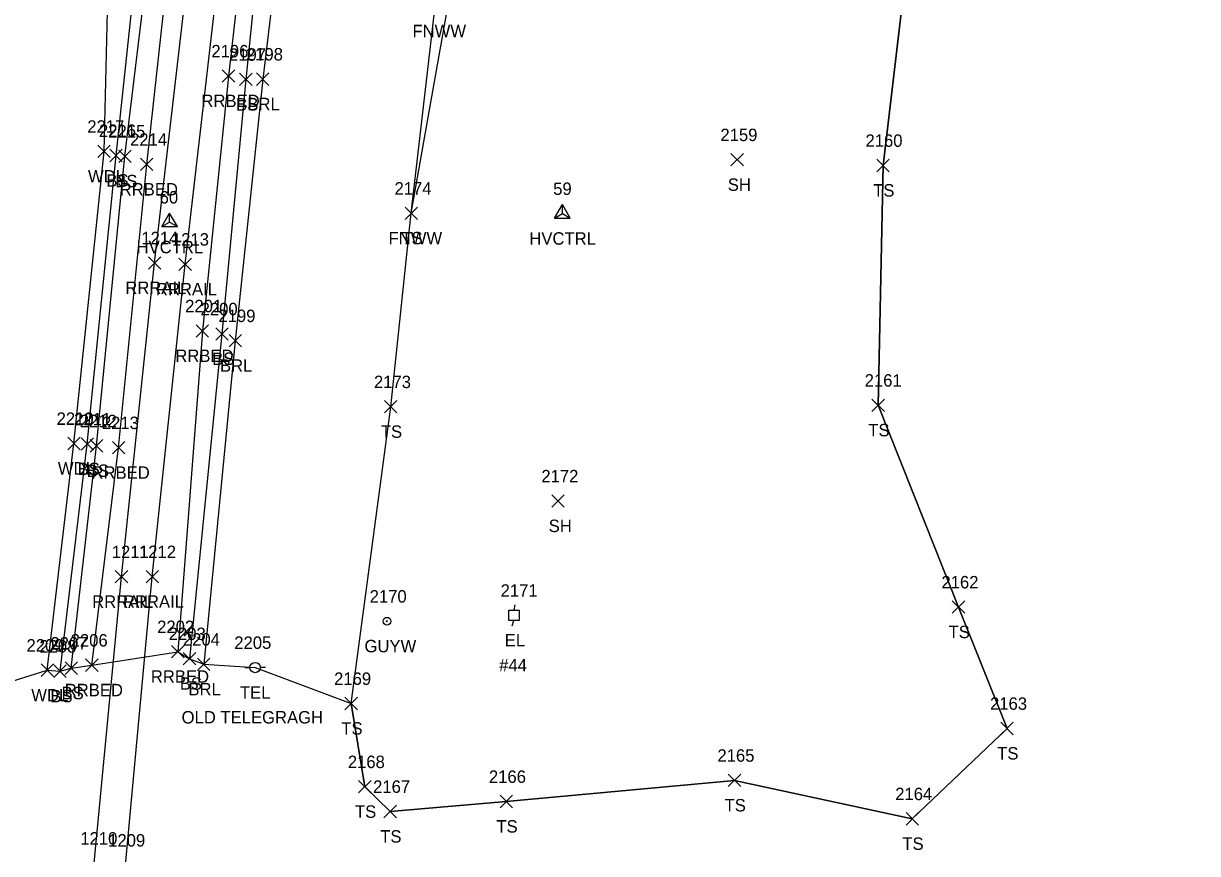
# Model space of a CAD drawing. Extents: x 1754529 to 1755810, y 621660 to 624656.
# Drawn here: x 1755616 to 1755804.8, y 623700.7 to 623834.2 of the extents above; entities that cross this region are included whole.
import ezdxf

# ---------------------------------------------------------------- set-up
doc = ezdxf.new("R2010")
doc.units = 0
for name, color, linetype in [('C_A', 7, 'Continuous'), ('C_I', 7, 'Continuous'), ('CPSM', 7, 'Continuous'), ('L_A', 7, 'Continuous'), ('L_I', 7, 'Continuous'), ('L_TIC', 7, 'Continuous'), ('LABL', 7, 'Continuous'), ('LAWA', 7, 'Continuous'), ('LELB', 7, 'Continuous'), ('LFNC', 7, 'Continuous'), ('LSOGP', 7, 'Continuous'), ('R_A', 7, 'Continuous'), ('R_I', 7, 'Continuous'), ('R_TIC', 7, 'Continuous'), ('RR', 7, 'Continuous'), ('RRB', 7, 'Continuous'), ('U_A', 7, 'Continuous'), ('U_C', 7, 'Continuous'), ('U_I', 7, 'Continuous'), ('UEPT', 7, 'Continuous'), ('UP', 7, 'Continuous'), ('UPGW', 7, 'Continuous')]:
    doc.layers.add(name, color=color, linetype=linetype)

msp = doc.modelspace()

# ---------------------------------------------------------------- linework, layer by layer
at = {"layer": 'CPSM'}
for p, q in [((1755701.4, 623802.89), (1755702.65, 623805.06)), ((1755703.9, 623802.89), (1755702.65, 623805.06)), ((1755702.65, 623803.61), (1755702.65, 623805.06)), ((1755638.27, 623801.51), (1755639.52, 623803.68)), ((1755640.77, 623801.51), (1755639.52, 623803.68)), ((1755639.52, 623802.23), (1755639.52, 623803.68)), ((1755701.4, 623802.89), (1755702.65, 623803.61)), ((1755701.4, 623802.89), (1755703.9, 623802.89)), ((1755702.65, 623803.61), (1755702.65, 623803.61)), ((1755702.65, 623803.61), (1755703.9, 623802.89)), ((1755638.27, 623801.51), (1755639.52, 623802.23)), ((1755638.27, 623801.51), (1755640.77, 623801.51)), ((1755639.52, 623802.23), (1755639.52, 623802.23)), ((1755639.52, 623802.23), (1755640.77, 623801.51))]:
    msp.add_line(p, q, dxfattribs=at)
at = {"layer": 'L_TIC'}
for points in [[(1755650.77, 623824.19), (1755652.77, 623826.19)], [(1755652.77, 623824.19), (1755650.77, 623826.19)], [(1755653.48, 623824.24), (1755655.48, 623826.24)], [(1755655.48, 623824.24), (1755653.48, 623826.24)], [(1755627.98, 623812.62), (1755629.98, 623814.62)], [(1755629.98, 623812.62), (1755627.98, 623814.62)], [(1755629.92, 623811.95), (1755631.92, 623813.95)], [(1755631.92, 623811.95), (1755629.92, 623813.95)], [(1755631.35, 623811.84), (1755633.35, 623813.84)], [(1755633.35, 623811.84), (1755631.35, 623813.84)], [(1755729.76, 623811.27), (1755731.76, 623813.27)], [(1755731.76, 623811.27), (1755729.76, 623813.27)], [(1755753.21, 623810.35), (1755755.21, 623812.35)], [(1755755.21, 623810.35), (1755753.21, 623812.35)], [(1755677.37, 623802.67), (1755679.37, 623804.67)], [(1755679.37, 623802.67), (1755677.37, 623804.67)], [(1755677.37, 623802.67), (1755679.37, 623804.67)], [(1755679.37, 623802.67), (1755677.37, 623804.67)], [(1755646.93, 623783.26), (1755648.93, 623785.26)], [(1755648.93, 623783.26), (1755646.93, 623785.26)], [(1755649.07, 623782.16), (1755651.07, 623784.16)], [(1755651.07, 623782.16), (1755649.07, 623784.16)], [(1755674.07, 623771.54), (1755676.07, 623773.54)], [(1755676.07, 623771.54), (1755674.07, 623773.54)], [(1755752.42, 623771.78), (1755754.42, 623773.78)], [(1755754.42, 623771.78), (1755752.42, 623773.78)], [(1755623.14, 623765.63), (1755625.14, 623767.63)], [(1755625.14, 623765.63), (1755623.14, 623767.63)], [(1755625.29, 623765.54), (1755627.29, 623767.54)], [(1755627.29, 623765.54), (1755625.29, 623767.54)], [(1755626.77, 623765.25), (1755628.77, 623767.25)], [(1755628.77, 623765.25), (1755626.77, 623767.25)], [(1755700.97, 623756.38), (1755702.97, 623758.38)], [(1755702.97, 623756.38), (1755700.97, 623758.38)], [(1755765.33, 623739.32), (1755767.33, 623741.32)], [(1755767.33, 623739.32), (1755765.33, 623741.32)], [(1755641.72, 623731.01), (1755643.72, 623733.01)], [(1755643.72, 623731.01), (1755641.72, 623733.01)], [(1755618.86, 623729.16), (1755620.86, 623731.16)], [(1755620.86, 623729.16), (1755618.86, 623731.16)], [(1755620.92, 623729), (1755622.92, 623731)], [(1755622.92, 623729), (1755620.92, 623731)], [(1755622.71, 623729.49), (1755624.71, 623731.49)], [(1755624.71, 623729.49), (1755622.71, 623731.49)], [(1755644, 623730.12), (1755646, 623732.12)], [(1755646, 623730.12), (1755644, 623732.12)], [(1755667.71, 623723.8), (1755669.71, 623725.8)], [(1755669.71, 623723.8), (1755667.71, 623725.8)], [(1755773.14, 623719.79), (1755775.14, 623721.79)], [(1755775.14, 623719.79), (1755773.14, 623721.79)], [(1755669.91, 623710.42), (1755671.91, 623712.42)], [(1755671.91, 623710.42), (1755669.91, 623712.42)], [(1755729.32, 623711.44), (1755731.32, 623713.44)], [(1755731.32, 623711.44), (1755729.32, 623713.44)], [(1755692.64, 623708.04), (1755694.64, 623710.04)], [(1755694.64, 623708.04), (1755692.64, 623710.04)], [(1755673.97, 623706.43), (1755675.97, 623708.43)], [(1755675.97, 623706.43), (1755673.97, 623708.43)], [(1755757.9, 623705.26), (1755759.9, 623707.26)], [(1755759.9, 623705.26), (1755757.9, 623707.26)]]:
    msp.add_lwpolyline(points, dxfattribs=at)
at = {"layer": 'LABL'}
msp.add_lwpolyline([(1755679.41, 624018.81), (1755672.58, 623965.56), (1755666.1, 623922.5), (1755661.18, 623881.21), (1755654.48, 623825.24), (1755650.07, 623783.16), (1755645, 623731.12)], dxfattribs=at)
at = {"layer": 'LAWA'}
msp.add_lwpolyline([(1755619.86, 623730.16), (1755624.14, 623766.63), (1755628.98, 623813.62), (1755630.26, 623865.45), (1755633.57, 623899.24), (1755639.63, 623936.66), (1755644.4, 623954.08), (1755644.69, 623975.95), (1755648.86, 624008.69), (1755659.88, 624048.72)], dxfattribs=at)
at = {"layer": 'LELB'}
for points in [[(1755621.92, 623730), (1755626.29, 623766.54), (1755630.92, 623812.95), (1755636.58, 623865.85), (1755640.01, 623898.18), (1755646.5, 623937.01), (1755651.75, 623974.07), (1755657.7, 624011.52), (1755662.62, 624047.83)], [(1755623.71, 623730.49), (1755627.77, 623766.25), (1755632.35, 623812.84), (1755638.78, 623865.94), (1755642.85, 623897.02), (1755648.59, 623936.85), (1755653.51, 623973.7), (1755658.98, 624011.28), (1755664.45, 624047.05)], [(1755677.5, 624019.45), (1755668.5, 623966.15), (1755663.47, 623922.18), (1755657.52, 623881.88), (1755651.77, 623825.19), (1755647.93, 623784.26), (1755642.72, 623732.01)], [(1755759.64, 623857.27), (1755754.21, 623811.35), (1755753.42, 623772.78), (1755766.33, 623740.32), (1755774.14, 623720.79), (1755758.9, 623706.26), (1755730.32, 623712.44), (1755693.64, 623709.04), (1755674.97, 623707.43), (1755670.91, 623711.42), (1755668.71, 623724.8), (1755675.07, 623772.54), (1755678.37, 623803.67), (1755691.4, 623877.41), (1755687.83, 623918.52), (1755691.1, 623961.39)]]:
    msp.add_lwpolyline(points, dxfattribs=at)
at = {"layer": 'LFNC'}
msp.add_lwpolyline([(1755678.37, 623803.67), (1755682.22, 623836.98), (1755686.15, 623877.78), (1755687.83, 623918.52)], dxfattribs=at)
at = {"layer": 'LSOGP'}
msp.add_lwpolyline([(1755585.86, 623719.5), (1755619.86, 623730.16), (1755621.92, 623730), (1755623.71, 623730.49), (1755627.02, 623730.97), (1755640.85, 623733.14), (1755642.72, 623732.01), (1755645, 623731.12), (1755653.26, 623730.59), (1755668.71, 623724.8), (1755670.91, 623711.42), (1755674.97, 623707.43), (1755693.64, 623709.04), (1755730.32, 623712.44), (1755758.9, 623706.26), (1755774.14, 623720.79), (1755766.33, 623740.32), (1755753.42, 623772.78), (1755754.21, 623811.35), (1755759.64, 623857.27)], dxfattribs=at)
at = {"layer": 'R_TIC'}
for points in [[(1755647.99, 623824.74), (1755649.99, 623826.74)], [(1755649.99, 623824.74), (1755647.99, 623826.74)], [(1755634.85, 623810.52), (1755636.85, 623812.52)], [(1755636.85, 623810.52), (1755634.85, 623812.52)], [(1755636.11, 623794.68), (1755638.11, 623796.68)], [(1755638.11, 623794.68), (1755636.11, 623796.68)], [(1755641.03, 623794.46), (1755643.03, 623796.46)], [(1755643.03, 623794.46), (1755641.03, 623796.46)], [(1755643.79, 623783.74), (1755645.79, 623785.74)], [(1755645.79, 623783.74), (1755643.79, 623785.74)], [(1755630.33, 623764.95), (1755632.33, 623766.95)], [(1755632.33, 623764.95), (1755630.33, 623766.95)], [(1755630.78, 623744.19), (1755632.78, 623746.19)], [(1755632.78, 623744.19), (1755630.78, 623746.19)], [(1755635.73, 623744.2), (1755637.73, 623746.2)], [(1755637.73, 623744.2), (1755635.73, 623746.2)], [(1755639.85, 623732.14), (1755641.85, 623734.14)], [(1755641.85, 623732.14), (1755639.85, 623734.14)], [(1755626.02, 623729.97), (1755628.02, 623731.97)], [(1755628.02, 623729.97), (1755626.02, 623731.97)]]:
    msp.add_lwpolyline(points, dxfattribs=at)
at = {"layer": 'RR'}
for points in [[(1755627.39, 623699.11), (1755631.78, 623745.19), (1755637.11, 623795.68), (1755642.45, 623841.98), (1755647.89, 623885.58), (1755654.04, 623931.54), (1755660.61, 623977.9), (1755666.29, 624016.06), (1755672.3, 624053.9), (1755679.64, 624097.76), (1755687.07, 624139.84), (1755694.5, 624180.62), (1755701.72, 624217.85), (1755709.31, 624256.23), (1755717.86, 624297.53), (1755724.56, 624328.91), (1755733.93, 624371.3), (1755743.26, 624412.4), (1755753.41, 624456.24), (1755764.06, 624501.26), (1755774.99, 624547.18), (1755787.52, 624599.52), (1755800.05, 624650.73)], [(1755632.43, 623698.79), (1755636.73, 623745.2), (1755642.03, 623795.46), (1755647.4, 623842), (1755652.81, 623884.87), (1755658.94, 623931.22), (1755665.5, 623977.61), (1755671.13, 624015.19), (1755677.17, 624053.23), (1755684.42, 624096.54), (1755692.03, 624139.27), (1755699.47, 624179.9), (1755706.47, 624216.55), (1755714.07, 624254.59), (1755722.62, 624295.88), (1755729.35, 624327.29), (1755738.69, 624369.66), (1755747.98, 624411.22), (1755758.14, 624454.7), (1755769.01, 624500.51), (1755779.76, 624545.7), (1755792.4, 624598.28), (1755804.75, 624649.74)]]:
    msp.add_lwpolyline(points, dxfattribs=at)
at = {"layer": 'RRB'}
for points in [[(1755627.02, 623730.97), (1755631.33, 623765.95), (1755635.85, 623811.52), (1755641.9, 623866.82), (1755645.93, 623895.6), (1755651.57, 623936.6), (1755656.7, 623972.5), (1755662.71, 624010.8), (1755667.32, 624046.39)], [(1755675.92, 624019.67), (1755666.85, 623966.35), (1755661.03, 623923.27), (1755655.33, 623881.88), (1755648.99, 623825.74), (1755644.79, 623784.74), (1755640.85, 623733.14)]]:
    msp.add_lwpolyline(points, dxfattribs=at)
at = {"layer": 'UEPT'}
for p, q in [((1755695.03, 623740.65), (1755694.86, 623739.81)), ((1755694.03, 623738.15), (1755694.03, 623739.81)), ((1755694.03, 623739.81), (1755695.69, 623739.81)), ((1755694.86, 623738.98), (1755694.86, 623738.98)), ((1755695.69, 623739.81), (1755695.69, 623738.15)), ((1755695.69, 623738.15), (1755694.03, 623738.15)), ((1755694.61, 623737.31), (1755694.86, 623738.15))]:
    msp.add_line(p, q, dxfattribs=at)
at = {"layer": 'UP'}
for p, q in [((1755651.6, 623730.58), (1755652.43, 623730.58)), ((1755653.26, 623730.59), (1755653.26, 623730.59)), ((1755654.93, 623730.59), (1755654.1, 623730.59)), ((1755654.1, 623730.59), (1755654.1, 623730.59)), ((1755654.93, 623730.59), (1755654.93, 623730.59))]:
    msp.add_line(p, q, dxfattribs=at)
msp.add_circle((1755653.26, 623730.59), 0.833, dxfattribs=at)
at = {"layer": 'UPGW'}
for radius in [0.625, 0.0833]:
    msp.add_circle((1755674.46, 623738.04), radius, dxfattribs=at)

# ---------------------------------------------------------------- texts
at = {"layer": 'C_A'}
for p in [(1755697.35, 623798.61), (1755634.21, 623797.23)]:
    msp.add_text('HVCTRL', height=2, dxfattribs=at).set_placement(p)
at = {"layer": 'C_I'}
for s, p in [('59', (1755701.18, 623806.61)), ('60', (1755637.92, 623805.23))]:
    msp.add_text(s, height=2, dxfattribs=at).set_placement(p)
at = {"layer": 'L_A'}
for s, p in [('FNWW', (1755678.56, 623831.98)), ('BS', (1755650.21, 623820.19)), ('BRL', (1755652.02, 623820.24)), ('WDL', (1755626.4, 623808.62)), ('BS', (1755629.36, 623807.95)), ('BS', (1755630.79, 623807.84)), ('SH', (1755729.25, 623807.27)), ('TS', (1755752.62, 623806.35)), ('FNWW', (1755674.72, 623798.67)), ('TS', (1755676.78, 623798.67)), ('BS', (1755646.37, 623779.26)), ('BRL', (1755647.62, 623778.16)), ('TS', (1755673.48, 623767.54)), ('TS', (1755751.83, 623767.78)), ('WDL', (1755621.56, 623761.63)), ('BS', (1755624.73, 623761.54)), ('BS', (1755626.21, 623761.25)), ('SH', (1755700.46, 623752.38)), ('TS', (1755764.74, 623735.32)), ('BS', (1755641.16, 623727.01)), ('WDL', (1755617.28, 623725.16)), ('BS', (1755620.36, 623725)), ('BS', (1755622.15, 623725.49)), ('BRL', (1755642.54, 623726.12)), ('TS', (1755667.12, 623719.8)), ('TS', (1755772.55, 623715.79)), ('TS', (1755669.32, 623706.42)), ('TS', (1755728.73, 623707.44)), ('TS', (1755673.38, 623702.43)), ('TS', (1755692.05, 623704.04)), ('TS', (1755757.31, 623701.26))]:
    msp.add_text(s, height=2, dxfattribs=at).set_placement(p)
at = {"layer": 'L_I'}
for s, p in [('2197', (1755649.08, 623828.19)), ('2198', (1755651.79, 623828.24)), ('2217', (1755626.29, 623816.62)), ('2216', (1755628.17, 623815.95)), ('2215', (1755629.66, 623815.84)), ('2159', (1755728.06, 623815.27)), ('2160', (1755751.38, 623814.35)), ('2174', (1755675.68, 623806.67)), ('2174', (1755675.68, 623806.67)), ('2200', (1755644.51, 623787.26)), ('2199', (1755647.37, 623786.16)), ('2173', (1755672.37, 623775.54)), ('2161', (1755751.25, 623775.78)), ('2210', (1755621.36, 623769.63)), ('2211', (1755624.17, 623769.54)), ('2212', (1755625.08, 623769.25)), ('2172', (1755699.28, 623760.38)), ('2162', (1755763.59, 623743.32)), ('2203', (1755639.38, 623735.01)), ('2209', (1755616.52, 623733.16)), ('2208', (1755618.58, 623733)), ('2207', (1755620.37, 623733.49)), ('2204', (1755641.66, 623734.12)), ('2169', (1755665.96, 623727.8)), ('2163', (1755771.4, 623723.79)), ('2165', (1755727.58, 623715.44)), ('2168', (1755668.17, 623714.42)), ('2166', (1755690.85, 623712.04)), ('2167', (1755672.23, 623710.43)), ('2164', (1755756.16, 623709.26))]:
    msp.add_text(s, height=2, dxfattribs=at).set_placement(p)
at = {"layer": 'R_A'}
for s, p in [('RRBED', (1755644.64, 623820.74)), ('RRBED', (1755631.5, 623806.52)), ('RRRAIL', (1755632.4, 623790.68)), ('RRRAIL', (1755637.32, 623790.46)), ('RRBED', (1755640.44, 623779.74)), ('RRBED', (1755626.97, 623760.95)), ('RRRAIL', (1755627.07, 623740.19)), ('RRRAIL', (1755632.02, 623740.2)), ('RRBED', (1755636.5, 623728.14)), ('RRBED', (1755622.66, 623725.97))]:
    msp.add_text(s, height=2, dxfattribs=at).set_placement(p)
at = {"layer": 'R_I'}
for s, p in [('2196', (1755646.24, 623828.74)), ('2214', (1755633.16, 623814.52)), ('1214', (1755634.98, 623798.68)), ('1213', (1755639.9, 623798.46)), ('2201', (1755642.02, 623787.74)), ('2213', (1755628.63, 623768.95)), ('1211', (1755630.22, 623748.19)), ('1212', (1755634.6, 623748.2)), ('2202', (1755637.52, 623736.14)), ('2206', (1755623.62, 623733.97)), ('1210', (1755625.17, 623702.11)), ('1209', (1755629.65, 623701.79))]:
    msp.add_text(s, height=2, dxfattribs=at).set_placement(p)
at = {"layer": 'U_A'}
for s, p in [('GUYW', (1755670.85, 623733.04)), ('EL', (1755693.39, 623733.98)), ('TEL', (1755650.82, 623725.59))]:
    msp.add_text(s, height=2, dxfattribs=at).set_placement(p)
at = {"layer": 'U_C'}
for s, p in [('#44', (1755692.5, 623729.98)), ('OLD TELEGRAGH', (1755641.45, 623721.59))]:
    msp.add_text(s, height=2, dxfattribs=at).set_placement(p)
at = {"layer": 'U_I'}
for s, p in [('2171', (1755692.73, 623741.98)), ('2170', (1755671.68, 623741.04)), ('2205', (1755649.92, 623733.59))]:
    msp.add_text(s, height=2, dxfattribs=at).set_placement(p)

doc.saveas('drawing.dxf')
